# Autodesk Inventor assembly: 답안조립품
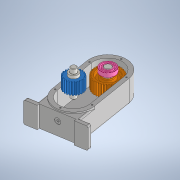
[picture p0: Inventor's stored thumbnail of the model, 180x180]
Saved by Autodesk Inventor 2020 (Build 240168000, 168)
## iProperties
Created: 2021-05
Part Number: 답안조립품
Document SubType Name: Assembly
Designer: OWner
Author: OWner
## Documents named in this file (15)
- C:\Users\OWner\Desktop\710507V1017\답안조립품.iam
- C:\Users\OWner\Desktop\710507V1017\답안도면.ipt
- C:\Users\OWner\Desktop\710507V1017\베어링 6001.ipt
- 베어링 6001.ipt
- C:\Users\OWner\Desktop\710507V1017\커버 B.ipt
- C:\Users\OWner\Desktop\710507V1017\볼트 M4.ipt
- C:\Users\OWner\Desktop\710507V1017\축 A.ipt
- C:\Users\OWner\Desktop\710507V1017\칼라.ipt
- C:\Users\OWner\Desktop\710507V1017\키 5 x 5 x 12.ipt
- C:\Users\OWner\Desktop\710507V1017\스퍼기어 A.ipt
- C:\Users\OWner\Desktop\710507V1017\베어링 6002.ipt
- 베어링 6002.ipt
- C:\Users\OWner\Desktop\710507V1017\축 B.ipt
- C:\Users\OWner\Desktop\710507V1017\키 4 x 4 x 12.ipt
- C:\Users\OWner\Desktop\710507V1017\스퍼기어 B.ipt
